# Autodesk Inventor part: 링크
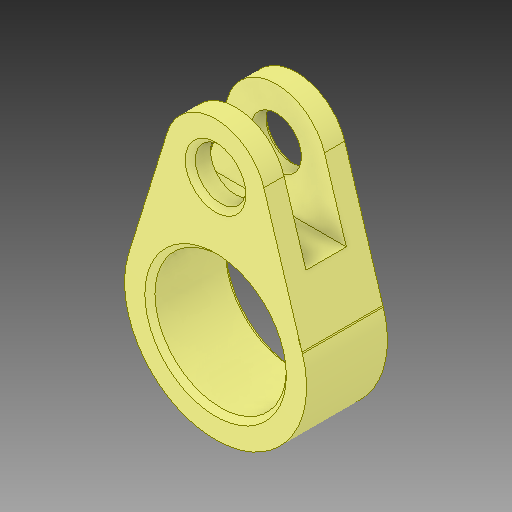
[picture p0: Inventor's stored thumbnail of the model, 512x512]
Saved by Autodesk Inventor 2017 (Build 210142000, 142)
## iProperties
Created: 2024-08
Part Number: 링크
Material: 일반
Document SubType Name: Modeling
Designer: MRC
Density: 1 g/cm^3
Appearance: 기본값
Author: jhkim
Sending System: Autodesk Inventor 2025
Preprocessor: ST-DEVELOPER v20
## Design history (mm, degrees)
feature "솔리드1"
node "솔리드2"
